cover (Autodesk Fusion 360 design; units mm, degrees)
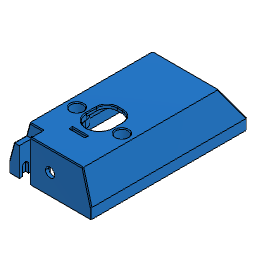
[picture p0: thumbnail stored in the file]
work_plane "Arbeitsebene" AlongDistance 0
sketch "Skizze1" plane through (-74.95, -18.8105, 23.4782) normal (0, 0, 1) x axis (1, 0, 0)
  line L1 (19.75, 71) -> (19.0964, 71)
  line L2 (19.0964, 71) -> (-19.0964, 71)
  line L3 (-19.0964, 71) -> (-19.75, 71)
  line L4 (-20, 70.75) -> (-19.75, 71)
  line L5 (-20, 70.75) -> (-20, 43)
  line L6 (20, 70.75) -> (20, 43)
  line L7 (20, 70.75) -> (19.75, 71)
  line L8 (19.2, 43) -> (20, 43)
  line L9 (-19.2, 43) -> (19.2, 43)
  line L10 (-20, 43) -> (-19.2, 43)
  line L11 (-20, 7) -> (-20, 31)
  line L12 (11.1, 31) -> (20, 31)
  line L13 (11.1, 31) -> (10.1, 31)
  line L14 (5.9, 31) -> (10.1, 31)
  line L15 (5.9, 31) -> (4.9, 31)
  line L16 (-4.9, 31) -> (4.9, 31)
  line L17 (-4.9, 31) -> (-5.9, 31)
  line L18 (-10.1, 31) -> (-5.9, 31)
  line L19 (-10.1, 31) -> (-11.1, 31)
  line L20 (-20, 31) -> (-11.1, 31)
  line L21 (20, 31) -> (20, 7)
  line L22 (-11.1, 7) -> (-20, 7)
  line L23 (-11.1, 7) -> (-10.1, 7)
  line L24 (-5.9, 7) -> (-10.1, 7)
  line L25 (-5.9, 7) -> (-4.9, 7)
  line L26 (4.9, 7) -> (-4.9, 7)
  line L27 (4.9, 7) -> (5.9, 7)
  line L28 (10.1, 7) -> (5.9, 7)
  line L29 (10.1, 7) -> (11.1, 7)
  line L30 (20, 7) -> (11.1, 7)
  line L31 (-19.2, 7) -> (-20, 7)
  line L32 (-20, 5) -> (-19.2, 5)
  line L33 (-20, 7) -> (-20, 5)
  line L34 (-5, 5) -> (-19.2, 5)
  line L35 (-5, 5) -> (-3, 5)
  line L36 (3, 5) -> (-3, 5)
  line L37 (3, 5) -> (5, 5)
  line L38 (5, 5) -> (19.2, 5)
  line L39 (19.2, 5) -> (20, 5)
  line L40 (20, 7) -> (19.2, 7)
  line L41 (20, 5) -> (20, 7)
  line L42 (-3, 7) -> (3, 7)
  line L43 (3, 7) -> (5, 7)
  line L44 (5, 7) -> (19.2, 7)
  line L45 (-19.2, 7) -> (-5, 7)
  line L46 (-5, 7) -> (-3, 7)
  line L47 (19.2, 31) -> (20, 31)
  line L48 (20, 33) -> (19.2, 33)
  line L49 (20, 31) -> (20, 33)
  line L50 (5, 33) -> (19.2, 33)
  line L51 (5, 33) -> (3, 33)
  line L52 (-3, 33) -> (3, 33)
  line L53 (-3, 33) -> (-5, 33)
  line L54 (-5, 33) -> (-19.2, 33)
  line L55 (-19.2, 33) -> (-20, 33)
  line L56 (-20, 31) -> (-19.2, 31)
  line L57 (-20, 33) -> (-20, 31)
  line L58 (3, 31) -> (-3, 31)
  line L59 (-3, 31) -> (-5, 31)
  line L60 (-5, 31) -> (-19.2, 31)
  line L61 (19.2, 31) -> (5, 31)
  line L62 (5, 31) -> (3, 31)
  line L63 (-9, 51) -> (9, 51)
  line L64 (19.2, 33) -> (-19.2, 33)
  line L65 (20, 33) -> (19.2, 33)
  line L66 (-19.2, 33) -> (-20, 33)
  line L67 (-20, 51) -> (-20, 43)
  line L68 (-20, 51) -> (-16.75, 51)
  line L69 (-16.75, 51) -> (-13.5, 51)
  line L70 (9, 43) -> (13.5, 43)
  line L71 (-13.5, 43) -> (-9, 43)
  line L72 (13.5, 51) -> (16.75, 51)
  line L73 (16.75, 51) -> (20, 51)
  line L74 (20, 51) -> (20, 43)
  line L75 (20, 33) -> (20, 43)
  line L76 (-20, 33) -> (-20, 43)
  line L77 (9, 51) -> (9, 43)
  line L78 (-9, 51) -> (-9, 43)
  line L79 (-13.5, 51) -> (-13.5, 43)
  line L80 (13.5, 51) -> (13.5, 43)
  line L81 (-7, -3) -> (7, -3)
  line L82 (-7, 5) -> (-7, -3)
  line L83 (-19.2, 5) -> (-7, 5)
  line L84 (-19.2, -5) -> (-19.2, 5)
  line L85 (-5.1228, -5) -> (-19.2, -5)
  line L86 (5.1228, -5) -> (-5.1228, -5)
  line L87 (19.2, -5) -> (5.1228, -5)
  line L88 (19.2, 5) -> (19.2, -5)
  line L89 (7, 5) -> (19.2, 5)
  line L90 (7, -3) -> (7, 5)
  line L91 (20, -5) -> (19.2, -5)
  line L92 (20, 5) -> (20, -5)
  line L93 (19.2, 5) -> (20, 5)
  line L94 (19.2, -5) -> (19.2, 5)
  line L95 (-19.2, -5) -> (-20, -5)
  line L96 (-19.2, 5) -> (-19.2, -5)
  line L97 (-20, 5) -> (-19.2, 5)
  line L98 (-20, -5) -> (-20, 5)
  line L99 (5, -6) -> (-5, -6)
  line L100 (5, -5) -> (5, -6)
  line L101 (-5, -5) -> (5, -5)
  line L102 (-5, -6) -> (-5, -5)
  line L103 (-5, -6) -> (-9, -6)
  line L104 (-5, -5) -> (-5, -6)
  line L105 (-5.1228, -5) -> (-5, -5)
  line L106 (-9, -5) -> (-5.1228, -5)
  line L107 (-9, -6) -> (-9, -5)
  line L108 (9, -6) -> (5, -6)
  line L109 (9, -5) -> (9, -6)
  line L110 (5.1228, -5) -> (9, -5)
  line L111 (5, -5) -> (5.1228, -5)
  line L112 (5, -6) -> (5, -5)
  circle C1 centre (0, 11.5) radius 1.2645
  circle C2 centre (11, 19) radius 1.2645
  circle C3 centre (-11, 19) radius 1.2645
  circle C4 centre (0, 26.5) radius 1.2645
  circle C5 centre (8, 26.5) radius 1.6
  circle C6 centre (-8, 26.5) radius 1.6
  circle C7 centre (8, 11.5) radius 1.6
  circle C8 centre (-8, 11.5) radius 1.6
extrude "Extrusion1" new body sketch "Skizze1" profile of L1 L2 L3 L4 L5 L6 L7 L11 L21 C1 C2 C3 C4 L33 L41 L49 L57 L74 L75 L76 L85 L87 L91 L92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 along normal blind 20
delete_face "Fläche löschen3"
delete_face "Fläche löschen4"
sketch "Skizze2" plane through (0, 0, 43.4782) normal (0, 0, 1) x axis (0, -1, 0)
  line L1 (23.8106, -94.95) -> (-52.1894, -94.9501)
  line L2 (23.8106, -79.95) -> (23.8106, -94.95)
  line L3 (24.8106, -79.95) -> (23.8106, -79.95)
  line L4 (24.8105, -69.95) -> (24.8106, -79.95)
  line L5 (23.8105, -69.95) -> (24.8105, -69.95)
  line L6 (23.8105, -54.95) -> (23.8105, -69.95)
  line L7 (-52.1895, -54.9501) -> (23.8105, -54.95)
  line L8 (-52.1894, -94.9501) -> (-52.1895, -54.9501)
  circle C1 centre (-0.1894, -85.95) radius 1.2645
  circle C2 centre (-0.1895, -63.95) radius 1.2645
  circle C3 centre (-0.1894, -85.95) radius 3
  circle C4 centre (-0.1895, -63.95) radius 3
  concentric C1 C3
  concentric C2 C4
  dimension "d109" diameter C3 = 6
  dimension "d112" diameter C4 = 6
extrude "Extrusion2" cut sketch "Skizze2" profile of C1 C2 C3 C4 against normal blind 15
sketch "Skizze3" plane through (0, 0, 43.4782) normal (0, 0, 1) x axis (0, -1, 0)
  line L1 (23.8106, -94.95) -> (-52.1894, -94.9501)
  line L2 (23.8106, -79.95) -> (23.8106, -94.95)
  line L3 (24.8106, -79.95) -> (23.8106, -79.95)
  line L4 (24.8105, -69.95) -> (24.8106, -79.95)
  line L5 (23.8105, -69.95) -> (24.8105, -69.95)
  line L6 (23.8105, -54.95) -> (23.8105, -69.95)
  line L7 (-52.1895, -54.9501) -> (23.8105, -54.95)
  line L8 (9.3106, -78.45) -> (9.3105, -71.45)
  line L9 (10.3105, -71.45) -> (10.3106, -78.45)
  line L10 (9.3105, -71.45) -> (10.3105, -71.45)
  line L11 (-10.1895, -59.95) -> (-10.1895, -66.7)
  line L12 (4.8105, -54.95) -> (-5.1895, -54.95)
  line L13 (9.8105, -62.5001) -> (9.8105, -59.95)
  line L14 (10.3106, -78.45) -> (9.3106, -78.45)
  line L15 (-8.1895, -68.7) -> (-0.1895, -68.7)
  line L16 (-0.1894, -81.2) -> (-8.1894, -81.2)
  line L17 (-10.1894, -83.2) -> (-10.1894, -89.95)
  line L18 (-5.1894, -94.95) -> (4.8106, -94.95)
  line L19 (9.8106, -89.95) -> (9.8106, -87.3999)
  line L20 (-10.1895, -66.7) -> (-10.1894, -83.2)
  line L21 (-10.1894, -81.2) -> (-8.1894, -81.2)
  line L22 (-10.1895, -68.7) -> (-8.1895, -68.7)
  line L23 (-52.1894, -94.9501) -> (-52.1895, -54.9501)
  circle C1 centre (-0.1895, -63.95) radius 3
  circle C2 centre (-0.1894, -85.95) radius 3
  arc A1 centre (-0.1894, -74.95) radius 15 clockwise from (10.6439, -64.5751) to (10.6439, -85.3249)
  arc A2 centre (-0.1894, -74.95) radius 6.25 clockwise from (-0.1895, -68.7) to (-0.1894, -81.2)
  circle C3 centre (-0.1895, -63.95) radius 1.6
  circle C4 centre (-0.1894, -85.95) radius 1.6
  arc A3 centre (-8.1895, -66.7) radius 2 clockwise from (-8.1895, -68.7) to (-10.1895, -66.7)
  arc A4 centre (-5.1895, -59.95) radius 5 clockwise from (-10.1895, -59.95) to (-5.1895, -54.95)
  arc A5 centre (4.8105, -59.95) radius 5 clockwise from (4.8105, -54.95) to (9.8105, -59.95)
  arc A6 centre (12.8105, -62.5001) radius 3 clockwise from (10.6439, -64.5751) to (9.8105, -62.5001)
  arc A7 centre (-8.1894, -83.2) radius 2 clockwise from (-10.1894, -83.2) to (-8.1894, -81.2)
  arc A8 centre (-5.1894, -89.95) radius 5 clockwise from (-5.1894, -94.95) to (-10.1894, -89.95)
  arc A9 centre (4.8106, -89.95) radius 5 clockwise from (9.8106, -89.95) to (4.8106, -94.95)
  arc A10 centre (12.8106, -87.3999) radius 3 clockwise from (9.8106, -87.3999) to (10.6439, -85.3249)
  point P35 (-10.1894, -83.2)
  point P45 (-10.1894, -83.2)
  point P23 (-10.1895, -66.7)
  point P46 (-10.1895, -66.7)
  point P34 (-8.1894, -81.2)
  point P47 (-8.1894, -81.2)
  point P48 (-10.1894, -81.2)
  point P24 (-8.1895, -68.7)
  point P49 (-8.1895, -68.7)
  point P50 (-10.1895, -68.7)
  coincident P35 P45
  coincident P23 P46
  coincident P34 P47
  coincident L20 P48
  tangent A7 L21
  coincident P24 P49
  coincident L20 P50
  tangent A3 L22
extrude "Extrusion3" cut sketch "Skizze3" profile of L8 L9 A2 L10 L14 L15 L16 L20 L21 L22 no distance stored
combine "Kombinieren1"
sketch "Skizze4" plane through (0, -23.8105, 0) normal (0, -1, 0) x axis (1, 0, 0)
  line L1 (-79.95, 23.4782) -> (-94.95, 23.4782)
  line L2 (-79.95, 43.4782) -> (-79.95, 23.4782)
  line L3 (-94.95, 43.4782) -> (-79.95, 43.4782)
  line L4 (-94.95, 23.4782) -> (-94.95, 43.4782)
  line L5 (-84.65, 35.9621) -> (-85.15, 35.9621)
  line L6 (-84.65, 25.0121) -> (-84.65, 35.9621)
  line L7 (-89.95, 25.0121) -> (-84.65, 25.0121)
  line L8 (-89.95, 35.9621) -> (-89.95, 25.0121)
  line L9 (-89.45, 35.9621) -> (-89.95, 35.9621)
  line L10 (-89.45, 36.7149) -> (-89.45, 35.9621)
  line L11 (-89.75, 36.7149) -> (-89.45, 36.7149)
  line L12 (-89.75, 37.6093) -> (-89.75, 36.7149)
  line L13 (-89.45, 37.6093) -> (-89.75, 37.6093)
  line L14 (-89.45, 38.3121) -> (-89.45, 37.6093)
  line L15 (-89.95, 38.3121) -> (-89.45, 38.3121)
  line L16 (-89.95, 41.0121) -> (-89.95, 38.3121)
  line L17 (-84.65, 41.0121) -> (-89.95, 41.0121)
  line L18 (-84.65, 38.3121) -> (-84.65, 41.0121)
  line L19 (-85.15, 38.3121) -> (-84.65, 38.3121)
  line L20 (-85.15, 37.6093) -> (-85.15, 38.3121)
  line L21 (-84.85, 37.6093) -> (-85.15, 37.6093)
  line L22 (-84.85, 36.7149) -> (-84.85, 37.6093)
  line L23 (-85.15, 36.7149) -> (-84.85, 36.7149)
  line L24 (-85.15, 35.9621) -> (-85.15, 36.7149)
  line L25 (-91.45, 26.0621) -> (-91.45, 29.0621)
  line L26 (-89.95, 41.0121) -> (-89.95, 43.5121)
  line L27 (-89.95, 41.0121) -> (-89.95, 38.3121)
  line L28 (-89.95, 26.0621) -> (-89.95, 25.0121)
  line L29 (-89.95, 38.3121) -> (-89.95, 29.0621)
  line L30 (-84.65, 43.5121) -> (-84.65, 41.0121)
  line L31 (-89.95, 43.5121) -> (-84.65, 43.5121)
  line L32 (-84.65, 29.1621) -> (-84.65, 38.3121)
  line L33 (-84.65, 25.0121) -> (-84.65, 26.1621)
  line L34 (-89.95, 25.0121) -> (-84.65, 25.0121)
  line L35 (-84.65, 41.0121) -> (-84.65, 38.3121)
  line L36 (-83.15, 29.1621) -> (-83.15, 26.1621)
  line L37 (-89.95, 26.0621) -> (-91.45, 26.0621)
  line L38 (-89.95, 29.0621) -> (-91.45, 29.0621)
  line L39 (-84.65, 29.1621) -> (-83.15, 29.1621)
  line L40 (-84.65, 26.1621) -> (-83.15, 26.1621)
  line L41 (-84.65, 38.3121) -> (-89.95, 38.3121)
  point P30 (-89.95, 38.3121)
  point P42 (-89.95, 38.3121)
  point P36 (-84.65, 38.3121)
  point P43 (-84.65, 38.3121)
  coincident P30 P42
  coincident P36 P43
extrude "Extrusion4" cut sketch "Skizze4" profile of L5 L6 L7 L8 L9 L10 L11 L12 L13 L14 L15 L19 L20 L21 L22 L23 L24 L28 L29 L32 L33 L34 L41 to an object
extrude "Extrusion15" cut sketch "Skizze4" profile of L6 L8 L25 L36 L37 L38 L39 L40 against normal blind 3
delete_face "Fläche löschen5"
delete_face "Fläche löschen6"
delete_face "Fläche löschen7"
delete_face "Fläche löschen8"
delete_face "Fläche löschen9"
delete_face "Fläche löschen10"
delete_face "Fläche löschen11"
delete_face "Fläche löschen12"
delete_face "Fläche löschen13"
chamfer "Fase2" distance 10 distance 15
chamfer "Fase3" distance 4 distance 15
shell "Schale" innerThickness 1.6
extrude "Extrusion5" add of existing geometry to an object
extrude "Extrusion6" add of existing geometry blind 1
fillet "Abrundung1" radius 5
extrude "Extrusion14" add of existing geometry blind 2
fillet "Abrundung5" radius 3
extrude "Extrusion16" add of existing geometry blind 1.99
delete_face "Fläche löschen26"
delete_face "Fläche löschen27"
delete_face "Fläche löschen16"
extrude "Extrusion9" cut of existing geometry blind -7
delete_face "Fläche löschen17"
delete_face "Fläche löschen18"
delete_face "Fläche löschen19"
delete_face "Fläche löschen20"
delete_face "Fläche löschen21"
delete_face "Fläche löschen24"
delete_face "Fläche löschen25"
fillet "Abrundung3" radius 5
sketch "Skizze5" plane through (0, -22.2105, 0) normal (0, 1, 0) x axis (-1, 0, 0)
  line L1 (83.05, 23.4782) -> (56.55, 23.4782)
  line L2 (81.55, 30.7621) -> (81.55, 24.5621)
  line L3 (83.05, 24.5621) -> (83.05, 23.4782)
  line L4 (60.1792, 41.8782) -> (83.05, 41.8782)
  line L5 (56.55, 28.2685) -> (60.1792, 41.8782)
  line L6 (56.55, 23.4782) -> (56.55, 28.2685)
  line L7 (68.7, 40.4782) -> (70.45, 40.4782)
  line L8 (68.7, 36.9782) -> (68.7, 40.4782)
  line L9 (70.45, 36.9782) -> (68.7, 36.9782)
  line L10 (68.7, 29.4782) -> (70.45, 29.4782)
  line L11 (68.7, 25.9782) -> (68.7, 29.4782)
  line L12 (70.45, 25.9782) -> (68.7, 25.9782)
  line L13 (81.2, 25.9782) -> (79.45, 25.9782)
  line L14 (81.2, 29.4782) -> (81.2, 25.9782)
  line L15 (79.45, 29.4782) -> (81.2, 29.4782)
  line L16 (81.2, 36.9782) -> (79.45, 36.9782)
  line L17 (81.2, 40.4782) -> (81.2, 36.9782)
  line L18 (79.45, 40.4782) -> (81.2, 40.4782)
  line L19 (81.3462, 43.4782) -> (81.133, 43.4782)
  line L20 (81.133, 43.4782) -> (68.767, 43.4782)
  line L21 (68.767, 43.4782) -> (68.5538, 43.4782)
  curve K1 (68.5538, 43.4782) -> (64.732, 41.7021)
  curve K2 (64.3601, 41.2008) -> (63.8349, 40.1311)
  curve K3 (64.732, 41.7021) -> (64.3601, 41.2008)
  line L22 (63.8104, 40.0593) -> (62.5001, 36.1285)
  line L23 (62.0258, 34.7055) -> (61.0896, 31.897)
  line L24 (62.5001, 36.1285) -> (62.0258, 34.7055)
  curve K4 (59.6415, 29.7177) -> (56.7065, 28.4912)
  curve K5 (59.95, 30.0122) -> (59.6415, 29.7177)
  line L25 (55.45, 28.4782) -> (54.95, 27.9782)
  line L26 (56.3462, 28.4782) -> (55.45, 28.4782)
  curve K6 (56.7065, 28.4912) -> (56.3462, 28.4782)
  line L27 (94.45, 28.4782) -> (94.95, 27.9782)
  line L28 (94.45, 28.4782) -> (93.5538, 28.4782)
  curve K7 (93.1935, 28.4912) -> (90.2585, 29.7177)
  curve K8 (93.5538, 28.4782) -> (93.1935, 28.4912)
  line L29 (88.8104, 31.897) -> (87.8742, 34.7055)
  curve K9 (90.2585, 29.7177) -> (89.95, 30.0122)
  line L30 (87.3999, 36.1285) -> (86.0896, 40.0593)
  line L31 (87.8742, 34.7055) -> (87.3999, 36.1285)
  curve K10 (86.0651, 40.1311) -> (85.5399, 41.2008)
  curve K11 (85.168, 41.7021) -> (81.3462, 43.4782)
  curve K12 (85.5399, 41.2008) -> (85.168, 41.7021)
  line L32 (54.95, 27.9782) -> (54.95, 23.9782)
  line L33 (59.95, 23.4782) -> (62.5001, 23.4782)
  line L34 (62.5001, 23.4782) -> (64.9209, 23.4782)
  line L35 (64.9209, 23.4782) -> (84.9791, 23.4782)
  line L36 (84.9791, 23.4782) -> (87.3999, 23.4782)
  line L37 (87.3999, 23.4782) -> (89.95, 23.4782)
  line L38 (89.95, 23.4782) -> (94.45, 23.4782)
  line L39 (55.45, 23.4782) -> (59.95, 23.4782)
  line L40 (54.95, 23.9782) -> (55.45, 23.4782)
  line L41 (94.95, 23.9782) -> (94.45, 23.4782)
  line L42 (94.95, 27.9782) -> (94.95, 23.9782)
  line L43 (79.45, 36.9782) -> (79.45, 40.4782)
  line L44 (79.45, 25.9782) -> (79.45, 29.4782)
  line L45 (70.45, 29.4782) -> (70.45, 25.9782)
  line L46 (70.45, 40.4782) -> (70.45, 36.9782)
  line L47 (83.05, 30.7621) -> (81.55, 30.7621)
  line L48 (81.55, 24.5621) -> (83.05, 24.5621)
  line L49 (83.05, 41.8782) -> (83.05, 30.7621)
  closed curve K13 centre (76.9792, 35.1826)
  arc A1 centre (56.3462, 33.4782) radius 5 clockwise from (61.0896, 31.897) to (59.95, 30.0122)
  arc A2 centre (93.5538, 33.4782) radius 5 clockwise from (89.95, 30.0122) to (88.8104, 31.897)
  closed curve K14 centre (72.9209, 35.1826)
extrude "Extrusion10" cut sketch "Skizze5" profile of L7 L8 L9 L10 L11 L12 L13 L14 L15 L16 L17 L18 L43 L44 L45 L46 along normal blind 35.326
fillet "Abrundung4" radius 0.5
extrude "Extrusion11" cut sketch "Skizze5" against normal blind 4.763
offset_faces "Flächen versetzen1" distance -1
sketch "Skizze6" plane through (-94.95, 0, 0) normal (-1, 0, 0) x axis (0, -1, 0)
  line L1 (-52.1895, 28.4782) -> (23.8105, 28.4782)
  line L2 (-52.1895, 23.4782) -> (-52.1895, 28.4782)
  line L3 (23.8105, 23.4782) -> (-52.1895, 23.4782)
  line L4 (23.8105, 28.4782) -> (23.8105, 23.4782)
  line L5 (23.8105, 38.3121) -> (23.8105, 41.0121)
  line L6 (23.8105, 31.9762) -> (23.8105, 35.9621)
  line L7 (23.8105, 30.2121) -> (23.8105, 30.5479)
  line L8 (23.8105, 25.0121) -> (23.8105, 25.1121)
  line L9 (23.8105, 36.7149) -> (23.8105, 35.9621)
  line L10 (23.8105, 37.6093) -> (23.8105, 36.7149)
  line L11 (23.8105, 38.3121) -> (23.8105, 37.6093)
  line L12 (19.2605, 41.2278) -> (19.2605, 40.0964)
  line L13 (17.8105, 38.3121) -> (11.8105, 38.3121)
  line L14 (21.3105, 43.5121) -> (20.3105, 43.5121)
  line L15 (11.8105, 37.5421) -> (11.8105, 38.3121)
  line L16 (11.8105, 28.7821) -> (11.8105, 34.5421)
  line L17 (11.8105, 25.0121) -> (11.8105, 25.7821)
  line L18 (17.8105, 41.0121) -> (17.8105, 38.3121)
  line L19 (22.3605, 40.0964) -> (22.3605, 41.2278)
  line L20 (11.8105, 25.0121) -> (23.8105, 25.0121)
  line L21 (24.5105, 30.2121) -> (24.5105, 25.1121)
  line L22 (10.3105, 26.4821) -> (10.3105, 26.0321)
  line L23 (10.3105, 28.5321) -> (10.3105, 28.0821)
  line L24 (10.3105, 35.2421) -> (10.3105, 34.7921)
  line L25 (10.3105, 37.2921) -> (10.3105, 36.8421)
  line L26 (0.3105, 28.0821) -> (0.3105, 26.4821)
  line L27 (0.3105, 36.8421) -> (0.3105, 35.2421)
  line L28 (23.8105, 30.2121) -> (24.5105, 30.2121)
  line L29 (23.8105, 25.1121) -> (24.5105, 25.1121)
  line L30 (11.8105, 25.7821) -> (10.3105, 26.0321)
  line L31 (11.8105, 28.7821) -> (10.3105, 28.5321)
  line L32 (11.8105, 34.5421) -> (10.3105, 34.7921)
  line L33 (11.8105, 37.5421) -> (10.3105, 37.2921)
  line L34 (10.3105, 26.4821) -> (0.3105, 26.4821)
  line L35 (10.3105, 28.0821) -> (0.3105, 28.0821)
  line L36 (10.3105, 35.2421) -> (0.3105, 35.2421)
  line L37 (10.3105, 36.8421) -> (0.3105, 36.8421)
  line L38 (17.8105, 38.3121) -> (23.8105, 38.3121)
  line L39 (17.8105, 43.5121) -> (17.8105, 38.3121)
  line L40 (23.8105, 43.5121) -> (17.8105, 43.5121)
  line L41 (23.8105, 38.3121) -> (23.8105, 43.5121)
  arc A1 centre (20.3105, 41.0121) radius 2.5 clockwise from (17.8105, 41.0121) to (20.3105, 43.5121)
  arc A2 centre (20.8105, 40.6621) radius 1.65 clockwise from (19.2605, 41.2278) to (22.3605, 41.2278)
  arc A3 centre (21.3105, 41.0121) radius 2.5 clockwise from (21.3105, 43.5121) to (23.8105, 41.0121)
  arc A4 centre (20.8105, 40.6621) radius 1.65 clockwise from (22.3605, 40.0964) to (19.2605, 40.0964)
  arc A5 centre (23.1105, 31.2621) radius 1 clockwise from (23.8105, 31.9762) to (23.8105, 30.5479)
  circle C1 centre (20.8105, 40.6621) radius 1.25
  point P7 (23.8105, 38.3121)
  point P49 (23.8105, 38.3121)
  concentric A2 C1
  horizontal L38
  vertical L39
  horizontal L40
  vertical L41
  coincident P7 P49
  dimension "d161" diameter C1 = 2.5
extrude "Extrusion13" cut sketch "Skizze6" profile of L5 L12 A1 A2 L14 L18 L19 A3 A4 C1 L38 L39 L40 L41 against normal blind 7.176
extrude "Extrusion12" cut sketch "Skizze6" profile of C1 against normal blind 14.407
offset_faces "Flächen versetzen2" distance -1
chamfer "Fase4" sketch "Skizze6" distance 0.55
fillet "Abrundung6" radius 5
chamfer "Fase5" sketch "Skizze6" distance 0.4
delete_face "Fläche löschen28"
delete_face "Fläche löschen29"
extrude "Extrusion17" add of existing geometry blind 0.882
chamfer "Fase6" distance 1.49
extrude "Extrusion18" cut of existing geometry blind -5.446
fillet "Abrundung7" radius 1
delete_face "Fläche löschen30"
delete_face "Fläche löschen31"
delete_face "Fläche löschen32"
sketch "Skizze7" plane through (0, 0, 23.4782) normal (0, 0, -1) x axis (0, 1, 0)
  line L1 (-15.6566, -84.65) -> (-23.8106, -84.65)
  line L2 (-15.6566, -83.05) -> (-15.6566, -84.65)
  line L3 (-18.9229, -83.05) -> (-15.6566, -83.05)
  curve K1 (-18.9229, -83.05) -> (-20.8106, -82.6439)
  line L4 (-22.2106, -82.6439) -> (-20.8106, -82.6439)
  line L5 (-22.2105, -56.55) -> (-22.2106, -82.6439)
  line L6 (50.5895, -56.5501) -> (-22.2105, -56.55)
  line L7 (50.5894, -93.3501) -> (50.5895, -56.5501)
  line L8 (-15.6566, -93.35) -> (50.5894, -93.3501)
  line L9 (-15.6566, -89.95) -> (-15.6566, -93.35)
  line L10 (-23.8106, -89.95) -> (-15.6566, -89.95)
  line L11 (-23.8106, -94.55) -> (-23.8106, -89.95)
  line L12 (-23.4106, -94.95) -> (-23.8106, -94.55)
  line L13 (51.7894, -94.9501) -> (-23.4106, -94.95)
  line L14 (52.1894, -94.5501) -> (51.7894, -94.9501)
  line L15 (52.1895, -55.3501) -> (52.1894, -94.5501)
  line L16 (51.7895, -54.9501) -> (52.1895, -55.3501)
  line L17 (-23.4105, -54.95) -> (51.7895, -54.9501)
  line L18 (-23.8105, -55.35) -> (-23.4105, -54.95)
  line L19 (-23.8106, -84.65) -> (-23.8105, -55.35)
  line L20 (-19.3106, -91.45) -> (-22.3106, -91.45)
  line L21 (-22.3106, -89.95) -> (-19.3106, -89.95)
  line L22 (-19.3106, -83.15) -> (-22.3106, -83.15)
  line L23 (-19.3106, -84.65) -> (-22.3106, -84.65)
  line L24 (-19.3106, -91.45) -> (-22.3106, -91.45)
  line L25 (-19.3106, -89.95) -> (-19.3106, -91.45)
  line L26 (-22.3106, -89.95) -> (-19.3106, -89.95)
  line L27 (-22.3106, -91.45) -> (-22.3106, -89.95)
  line L28 (-19.3106, -84.65) -> (-22.3106, -84.65)
  line L29 (-19.3106, -83.15) -> (-19.3106, -84.65)
  line L30 (-22.3106, -83.15) -> (-19.3106, -83.15)
  line L31 (-22.3106, -84.65) -> (-22.3106, -83.15)
  point P24 (-19.3106, -89.95)
  point P32 (-19.3106, -89.95)
  point P22 (-22.3106, -91.45)
  point P30 (-22.3106, -91.45)
  point P27 (-19.3106, -83.15)
  point P36 (-19.3106, -83.15)
  point P28 (-22.3106, -84.65)
  point P34 (-22.3106, -84.65)
  horizontal L24
  vertical L25
  horizontal L26
  vertical L27
  coincident P24 P32
  coincident P22 P30
  horizontal L28
  vertical L29
  horizontal L30
  vertical L31
  coincident P27 P36
  coincident P28 P34
extrude "Extrusion19" cut sketch "Skizze7" profile of L1 L10 L20 L21 L22 L23 L24 L25 L26 L27 L28 L29 L30 L31 against normal blind 4
delete_face "Fläche löschen33"
delete_face "Fläche löschen34"
copy_paste_bodies "Körper kopieren/einfügen1"
copy_paste_bodies "Körper kopieren/einfügen2"
copy_paste_bodies "Körper kopieren/einfügen3"
combine "Kombinieren1"
delete_face "Fläche löschen1"
delete_face "Fläche löschen2"
delete_face "Fläche löschen3"
loft "Erhebung"
delete_face "Fläche löschen4"
sketch "Skizze1" plane through (0, -4.2, 0) normal (0, 1, 0) x axis (-1, 0, 0)
  line L1 (10, 10.4559) -> (-10, 8.152)
  line L2 (13.1791, 7) -> (10, 10.4559)
  line L3 (18.9403, 7) -> (13.1791, 7)
  line L4 (20, 8.152) -> (18.9403, 7)
  line L5 (20, 15.848) -> (20, 8.152)
  line L6 (18.9403, 17) -> (20, 15.848)
  line L7 (-19.1522, 17) -> (18.9403, 17)
  line L8 (-20, 16.0784) -> (-19.1522, 17)
  line L9 (-20, 10.4559) -> (-20, 16.0784)
  line L10 (-16.8209, 7) -> (-20, 10.4559)
  line L11 (-11.0597, 7) -> (-16.8209, 7)
  line L12 (-10, 8.152) -> (-11.0597, 7)
  circle C1 centre (-15, 12) radius 1.45
  circle C2 centre (15, 12) radius 1.45
  circle C3 centre (0, 7) radius 7
  circle C4 centre (0, 7) radius 5.5
  circle C5 centre (-10, 27) radius 3
  circle C6 centre (0, 7) radius 8
  circle C7 centre (-10, 27) radius 3.5
  dimension "d202_1" = 1
  dimension "d203_1" = 0.5
extrude "Extrusion1" cut sketch "Skizze1" profile of L1 C6 C7 no distance stored
delete_face "Fläche löschen5"
offset_faces "Flächen versetzen1" distance 0.85
delete_face "Fläche löschen6"
draft "Entwurf" Angle1 5.8 Angle2 0
delete_face "Fläche löschen7"
extrude "Extrusion2" new body of existing geometry blind 8
extrude "Extrusion3" add of existing geometry blind 8
extrude "Extrusion4" cut of existing geometry blind -24
extrude "Extrusion5" cut of existing geometry blind -13.573
delete_face "Fläche löschen8"
offset_faces "Flächen versetzen2" distance -2
extrude "Extrusion6" add of existing geometry blind 0.497
delete_face "Fläche löschen9"
delete_face "Fläche löschen10"
delete_face "Fläche löschen11"
delete_face "Fläche löschen12"
offset_faces "Flächen versetzen3" distance 6.24
delete_face "Fläche löschen13"
delete_face "Fläche löschen14"
offset_faces "Flächen versetzen4" distance 0.8
chamfer "Fase1" distance 4
delete_face "Fläche löschen15"
chamfer "Fase2" distance 5.323 distance 4.38
delete_face "Fläche löschen16"
delete_face "Fläche löschen17"
chamfer "Fase3" distance 4.08 distance 6.881
offset_faces "Flächen versetzen5" distance 1
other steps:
base_feature "Basiselement1"
base_feature "Basiselement2"
base_feature "Basiselement3"
create_component "Komponente erstellen"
